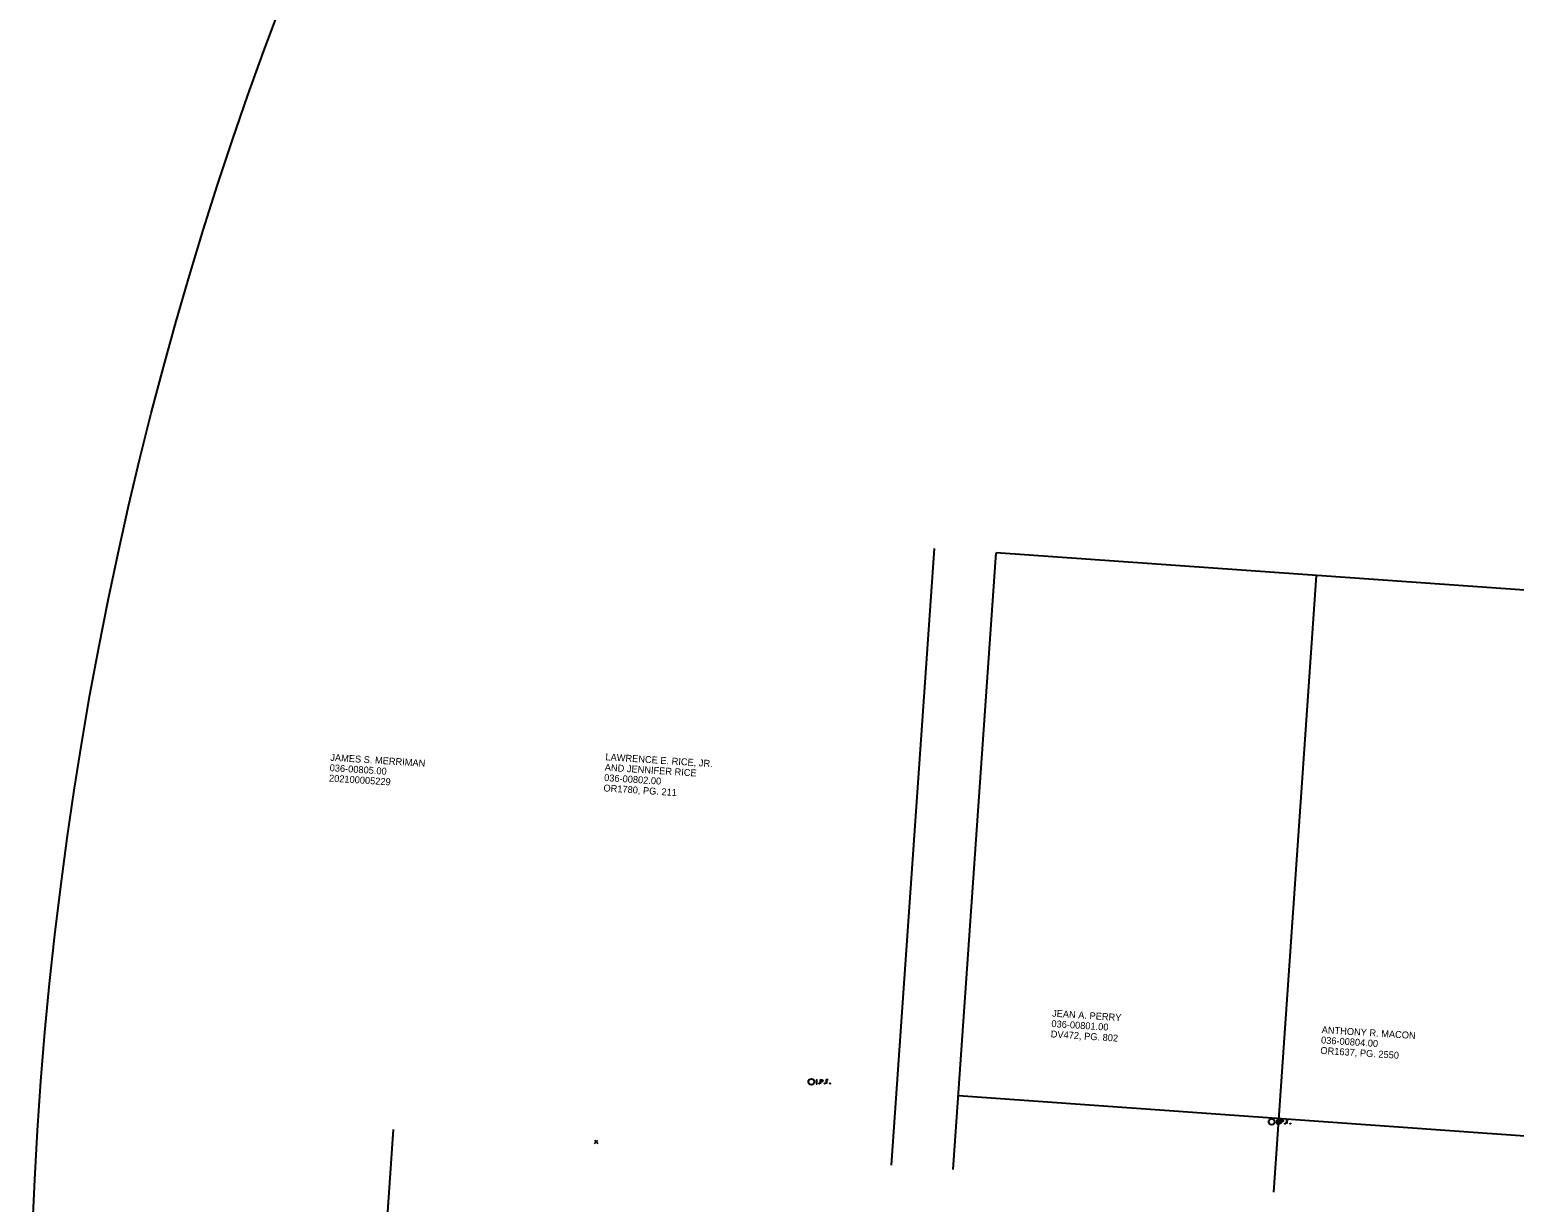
# Model space of a CAD drawing. Extents: x 1898254 to 1901377, y 701554 to 704886.
# Drawn here: x 1898254 to 1898855, y 703301 to 703775 of the extents above; entities that cross this region are included whole.
import ezdxf

# ---------------------------------------------------------------- set-up
doc = ezdxf.new("R2010")
doc.units = 0
for name, color, linetype in [('DV_X_Property_Line', 7, 'Continuous'), ('DV_X_Text', 7, 'Continuous'), ('RW_X_CL', 7, 'Continuous'), ('RW_X_Fee_RW', 7, 'Continuous'), ('SC_Scratch2', 7, 'Continuous'), ('SC_Scratch5', 7, 'Continuous'), ('SV_X_Mon_Cells_Found', 7, 'Continuous'), ('SV_X_Random_Point', 7, 'Continuous')]:
    doc.layers.add(name, color=color, linetype=linetype)

msp = doc.modelspace()

# ---------------------------------------------------------------- linework, layer by layer
at = {"layer": 'DV_X_Property_Line'}
for p, q in [((1898628.06, 703314.3), (1898645.43, 703563.69)), ((1898994.39, 703538.88), (1898645.43, 703563.69)), ((1898757.73, 703305.08), (1898775.1, 703554.47))]:
    msp.add_line(p, q, dxfattribs=at)
at = {"layer": 'RW_X_CL'}
for p, q in [((1898603.12, 703316.03), (1898620.49, 703565.43)), ((1898383.79, 703074.9), (1898401.58, 703330.4))]:
    msp.add_line(p, q, dxfattribs=at)
at = {"layer": 'RW_X_Fee_RW'}
msp.add_line((1898630.14, 703344.22), (1899526.13, 703280.51), dxfattribs=at)
at = {"layer": 'SC_Scratch2'}
msp.add_circle((1899815.76, 703229.84), 1561.35, dxfattribs=at)
at = {"layer": 'SC_Scratch5'}
msp.add_line((1898630.14, 703344.22), (1899526.13, 703280.51), dxfattribs=at)
at = {"layer": 'SV_X_Mon_Cells_Found'}
for points in [[(1898572.68, 703350.57), (1898573.04, 703350.57)], [(1898572.68, 703348.97), (1898573.04, 703348.97)], [(1898572.86, 703348.97), (1898572.86, 703350.57)], [(1898573.82, 703349.19), (1898573.87, 703349.19), (1898573.91, 703349.16), (1898573.94, 703349.11), (1898573.94, 703349.05), (1898573.91, 703349), (1898573.87, 703348.97), (1898573.82, 703348.97), (1898573.79, 703349), (1898573.75, 703349.05), (1898573.75, 703349.11), (1898573.79, 703349.16), (1898573.82, 703349.19)], [(1898574.42, 703348.97), (1898574.42, 703350.57), (1898574.95, 703350.57), (1898575.01, 703350.56), (1898575.09, 703350.53), (1898575.12, 703350.51), (1898575.15, 703350.48), (1898575.2, 703350.42), (1898575.23, 703350.36), (1898575.25, 703350.26), (1898575.25, 703350.11), (1898575.24, 703350.06), (1898575.22, 703349.98), (1898575.17, 703349.89), (1898575.13, 703349.85), (1898575.1, 703349.83), (1898575.04, 703349.8), (1898574.95, 703349.79), (1898574.42, 703349.79)], [(1898576.07, 703349.19), (1898576.12, 703349.19), (1898576.16, 703349.16), (1898576.19, 703349.11), (1898576.19, 703349.05), (1898576.16, 703349), (1898576.12, 703348.97), (1898576.07, 703348.97), (1898576.03, 703349), (1898576, 703349.05), (1898576, 703349.11), (1898576.03, 703349.16), (1898576.07, 703349.19)], [(1898577.43, 703350.57), (1898576.67, 703350.57), (1898576.67, 703348.97)], [(1898576.67, 703349.79), (1898577.21, 703349.79)], [(1898578.22, 703349.19), (1898578.27, 703349.19), (1898578.3, 703349.16), (1898578.34, 703349.11), (1898578.34, 703349.05), (1898578.3, 703349), (1898578.27, 703348.97), (1898578.22, 703348.97), (1898578.18, 703349), (1898578.15, 703349.05), (1898578.15, 703349.11), (1898578.18, 703349.16), (1898578.22, 703349.19)], [(1898758.93, 703334.36), (1898759.28, 703334.36)], [(1898758.93, 703332.76), (1898759.28, 703332.76)], [(1898759.11, 703332.76), (1898759.11, 703334.36)], [(1898760.07, 703332.97), (1898760.12, 703332.97), (1898760.16, 703332.95), (1898760.19, 703332.9), (1898760.19, 703332.83), (1898760.16, 703332.78), (1898760.12, 703332.76), (1898760.07, 703332.76), (1898760.03, 703332.78), (1898760, 703332.83), (1898760, 703332.9), (1898760.03, 703332.95), (1898760.07, 703332.97)], [(1898760.67, 703332.76), (1898760.67, 703334.36), (1898761.2, 703334.36), (1898761.26, 703334.34), (1898761.33, 703334.32), (1898761.37, 703334.29), (1898761.4, 703334.27), (1898761.45, 703334.21), (1898761.48, 703334.14), (1898761.5, 703334.04), (1898761.5, 703333.89), (1898761.49, 703333.84), (1898761.47, 703333.76), (1898761.42, 703333.68), (1898761.38, 703333.64), (1898761.35, 703333.61), (1898761.29, 703333.59), (1898761.2, 703333.58), (1898760.67, 703333.58)], [(1898762.32, 703332.97), (1898762.37, 703332.97), (1898762.4, 703332.95), (1898762.44, 703332.9), (1898762.44, 703332.83), (1898762.4, 703332.78), (1898762.37, 703332.76), (1898762.32, 703332.76), (1898762.28, 703332.78), (1898762.25, 703332.83), (1898762.25, 703332.9), (1898762.28, 703332.95), (1898762.32, 703332.97)], [(1898763.68, 703334.36), (1898762.92, 703334.36), (1898762.92, 703332.76)], [(1898762.92, 703333.58), (1898763.46, 703333.58)], [(1898764.47, 703332.97), (1898764.52, 703332.97), (1898764.55, 703332.95), (1898764.59, 703332.9), (1898764.59, 703332.83), (1898764.55, 703332.78), (1898764.52, 703332.76), (1898764.47, 703332.76), (1898764.43, 703332.78), (1898764.4, 703332.83), (1898764.4, 703332.9), (1898764.43, 703332.95), (1898764.47, 703332.97)]]:
    msp.add_lwpolyline(points, dxfattribs=at)
for centre in [(1898570.67, 703349.77), (1898756.92, 703333.56)]:
    msp.add_circle(centre, 1.2, dxfattribs=at)
at = {"layer": 'SV_X_Random_Point'}
for p, q in [((1898482.97, 703324.84), (1898484.31, 703326.17)), ((1898482.97, 703326.17), (1898484.31, 703324.84))]:
    msp.add_line(p, q, dxfattribs=at)

# ---------------------------------------------------------------- texts
at = {"layer": 'DV_X_Text'}
for s, p in [('036-00805.00', (1898375.71, 703475.38)), ('JAMES S. MERRIMAN', (1898375.98, 703479.58)), ('AND JENNIFER RICE', (1898487.02, 703475.57)), ('LAWRENCE E. RICE, JR. ', (1898487.29, 703479.77)), ('202100005229', (1898375.44, 703471.19)), ('036-00802.00', (1898486.75, 703471.38)), ('OR1780, PG. 211', (1898486.48, 703467.19)), ('036-00801.00', (1898667.72, 703371.91)), ('JEAN A. PERRY', (1898667.99, 703376.1)), ('DV472, PG. 802', (1898667.46, 703367.72)), ('ANTHONY R. MACON ', (1898777.08, 703369.46)), ('OR1637, PG. 2550', (1898776.54, 703361.08)), ('036-00804.00', (1898776.81, 703365.27))]:
    msp.add_text(s, height=2.8, rotation=356.3351, dxfattribs=at).set_placement(p)

doc.saveas('drawing.dxf')
